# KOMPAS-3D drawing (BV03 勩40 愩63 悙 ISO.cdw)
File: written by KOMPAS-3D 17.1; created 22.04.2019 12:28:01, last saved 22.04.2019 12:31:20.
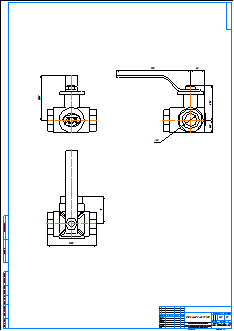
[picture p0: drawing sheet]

Sheet 1: A1, portrait

Title block, sheet 1: name: BV03 Ду40 Ру63 РР ISO; material: Внимание! Данный продукт является объектом авторского права ООО «Торговый Дом АДЛ». / Запрещается изменение, копирование, распространение / (в том числе путем копирования на другие сайты и ресурсы в Интернете) / или любое иное использование информации и объектов без предварительного / согласия правообладателя (ООО «Торговый Дом АДЛ»).; mass: 3,41; sheets: 1; organisation: ООО "Торговый дом АДЛ"; sheet format: A1

Views: Спереди 1, Проекционный вид 2, Проекционный вид 3
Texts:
  user
Dimensions and other numbers on the sheet: 112,5; 125,5; 70; 188; 36; 87,5; 32; 32,5; 1:1; 1; 3,41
